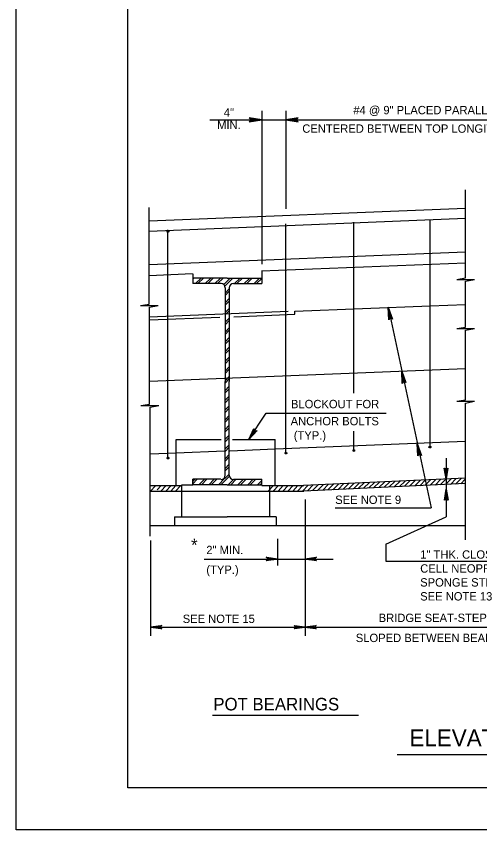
# Model space of a CAD drawing. Extents: x 640009 to 641706, y 298547 to 299735.
# Drawn here: x 640009.5 to 640175.7, y 298547.2 to 298839.2 of the extents above; entities that cross this region are included whole.
import ezdxf

# ---------------------------------------------------------------- set-up
doc = ezdxf.new("R2010")
doc.units = 0
doc.layers.add('1', color=7, linetype='Continuous')
doc.layers.add('PLT-BNDY', color=7, linetype='Continuous')

msp = doc.modelspace()

# ---------------------------------------------------------------- linework, layer by layer
at = {"layer": '1'}
for p, q in [((640049.47, 298562.17), (640049.47, 299126.17)), ((640049.47, 298562.17), (640049.47, 299126.17)), ((640097.48, 298805.29), (640097.48, 298750.25)), ((640106.11, 298805.29), (640106.11, 298770.05)), ((640078.94, 298802.06), (640270.39, 298802.06)), ((640170.61, 298745.27), (640170.61, 298776.9)), ((640057.11, 298735.87), (640057.11, 298770.62)), ((640057.11, 298765.75), (640170.61, 298770.37)), ((640057.11, 298762.12), (640170.61, 298766.74)), ((640157.86, 298684.37), (640157.86, 298766.13)), ((640106.11, 298682.25), (640106.11, 298764.69)), ((640130.48, 298703.87), (640130.48, 298765.27)), ((640063.86, 298680.5), (640063.86, 298762.5)), ((640057.11, 298750.12), (640170.61, 298754.62)), ((640097.45, 298747.8), (640170.61, 298750.74)), ((640057.11, 298746.12), (640072.65, 298746.83)), ((640072.73, 298746.8), (640072.73, 298743.25)), ((640097.48, 298747.75), (640097.48, 298743.25)), ((640085.11, 298745.25), (640072.73, 298745.25)), ((640085.11, 298745.25), (640072.73, 298745.25)), ((640072.73, 298745.25), (640072.73, 298743.25)), ((640085.11, 298745.25), (640072.73, 298745.25)), ((640072.73, 298745.25), (640072.73, 298744.25)), ((640085.11, 298745.25), (640072.73, 298745.25)), ((640072.73, 298745.25), (640072.73, 298743.25)), ((640082.86, 298743.25), (640072.73, 298743.25)), ((640082.86, 298743.25), (640072.73, 298743.25)), ((640082.86, 298743.25), (640072.73, 298743.25)), ((640085.11, 298745.25), (640097.48, 298745.25)), ((640085.11, 298745.25), (640097.48, 298745.25)), ((640085.11, 298745.25), (640097.48, 298745.25)), ((640085.11, 298745.25), (640097.48, 298745.25)), ((640087.36, 298743.25), (640097.48, 298743.25)), ((640087.36, 298743.25), (640097.48, 298743.25)), ((640087.36, 298743.25), (640097.48, 298743.25)), ((640097.48, 298745.25), (640097.48, 298743.25)), ((640097.48, 298745.25), (640097.48, 298744.25)), ((640097.48, 298745.25), (640097.48, 298743.25)), ((640167.48, 298744.77), (640170.61, 298745.27)), ((640167.48, 298744.77), (640173.86, 298744.77)), ((640170.61, 298744.12), (640173.86, 298744.77)), ((640170.61, 298735.8), (640170.61, 298744.12)), ((640170.73, 298744.77), (640170.73, 298744.77)), ((640084.36, 298741.75), (640084.36, 298708.12)), ((640084.36, 298741.75), (640084.36, 298708.12)), ((640084.36, 298741.75), (640084.36, 298708.12)), ((640085.86, 298741.75), (640085.86, 298708.12)), ((640085.86, 298741.75), (640085.86, 298708.12)), ((640085.86, 298741.75), (640085.86, 298708.12)), ((640053.98, 298735.37), (640057.11, 298735.87)), ((640053.98, 298735.37), (640060.36, 298735.37)), ((640057.23, 298734.75), (640060.36, 298735.37)), ((640057.23, 298735.37), (640057.23, 298735.37)), ((640057.23, 298700), (640057.23, 298734.75)), ((640109.36, 298733.37), (640157.86, 298735.29)), ((640142.86, 298734.75), (640158.21, 298662.75)), ((640157.86, 298735.29), (640170.61, 298735.8)), ((640170.61, 298727.63), (640170.61, 298735.8)), ((640057.23, 298731.37), (640106.98, 298733.37)), ((640057.23, 298730.25), (640082.48, 298731.25)), ((640087.48, 298731.37), (640109.36, 298732.25)), ((640109.36, 298732.25), (640109.36, 298733.37)), ((640167.48, 298727.13), (640170.61, 298727.63)), ((640167.48, 298727.13), (640173.86, 298727.13)), ((640170.61, 298726.48), (640173.86, 298727.13)), ((640170.61, 298701.5), (640170.61, 298726.48)), ((640170.73, 298727.13), (640170.73, 298727.13)), ((640057.23, 298708.25), (640170.61, 298712.76)), ((640084.36, 298674.5), (640084.36, 298708.12)), ((640084.36, 298674.5), (640084.36, 298708.12)), ((640084.36, 298674.5), (640084.36, 298708.12)), ((640085.86, 298674.5), (640085.86, 298708.12)), ((640085.86, 298674.5), (640085.86, 298708.12)), ((640085.86, 298674.5), (640085.86, 298708.12)), ((640054.11, 298699.5), (640057.23, 298700)), ((640054.11, 298699.5), (640060.61, 298699.5)), ((640057.36, 298699.5), (640057.36, 298699.5)), ((640057.48, 298698.87), (640060.61, 298699.5)), ((640057.48, 298652.62), (640057.48, 298698.87)), ((640167.48, 298701), (640170.61, 298701.5)), ((640167.48, 298701), (640173.86, 298701)), ((640170.61, 298700.35), (640173.86, 298701)), ((640170.61, 298651.25), (640170.61, 298700.35)), ((640170.73, 298701), (640170.73, 298701)), ((640092.73, 298687.12), (640099.11, 298696.75)), ((640099.11, 298696.75), (640142.11, 298696.75)), ((640130.48, 298683.25), (640130.48, 298690.25)), ((640066.86, 298670.62), (640066.86, 298687.25)), ((640066.86, 298687.25), (640082.98, 298687.25)), ((640086.98, 298687.25), (640102.36, 298687.25)), ((640102.36, 298670.75), (640102.36, 298687.25)), ((640102.36, 298683.91), (640170.61, 298686.62)), ((640057.48, 298682.12), (640066.86, 298682.44)), ((640066.86, 298682.44), (640084.11, 298683.15)), ((640086.08, 298683.23), (640102.36, 298683.91)), ((640163.61, 298680.61), (640163.61, 298659.54)), ((640082.86, 298673), (640072.73, 298673)), ((640072.73, 298671), (640072.73, 298673)), ((640082.86, 298673), (640072.73, 298673)), ((640072.73, 298671), (640072.73, 298673)), ((640082.86, 298673), (640072.73, 298673)), ((640072.73, 298671), (640072.73, 298673)), ((640087.36, 298673), (640097.48, 298673)), ((640087.36, 298673), (640097.48, 298673)), ((640087.36, 298673), (640097.48, 298673)), ((640097.48, 298671), (640097.48, 298673)), ((640097.48, 298671), (640097.48, 298673)), ((640097.48, 298671), (640097.48, 298673)), ((640170.61, 298673.35), (640112.48, 298670.75)), ((640057.48, 298670.75), (640068.73, 298670.75)), ((640068.73, 298671), (640072.73, 298671)), ((640068.73, 298670.75), (640068.73, 298659.5)), ((640085.11, 298671), (640072.73, 298671)), ((640085.11, 298671), (640072.73, 298671)), ((640085.11, 298671), (640072.73, 298671)), ((640085.11, 298671), (640097.48, 298671)), ((640085.11, 298671), (640097.48, 298671)), ((640085.11, 298671), (640097.48, 298671)), ((640097.48, 298670.75), (640100.23, 298670.75)), ((640100.23, 298670.75), (640100.23, 298659.5)), ((640100.23, 298670.75), (640112.61, 298670.75)), ((640170.61, 298671.47), (640112.61, 298668.75)), ((640057.48, 298668.75), (640112.61, 298668.75)), ((640113.11, 298665.75), (640113.11, 298616.74)), ((640123.84, 298662.75), (640158.21, 298662.75)), ((640066.23, 298659.5), (640066.23, 298656.37)), ((640066.23, 298659.5), (640085.11, 298659.5)), ((640102.73, 298659.5), (640085.11, 298659.5)), ((640102.73, 298659.5), (640102.73, 298656.37)), ((640141.96, 298649.74), (640163.61, 298659.54)), ((640057.48, 298656.37), (640170.61, 298656.37)), ((640057.61, 298651), (640057.61, 298616.74)), ((640103.11, 298651.62), (640103.11, 298642)), ((640141.96, 298649.74), (640141.96, 298643.6)), ((640076.84, 298644.37), (640103.11, 298644.37)), ((640103.11, 298644.37), (640113.11, 298644.37)), ((640113.11, 298644.37), (640123.11, 298644.37)), ((640141.96, 298643.6), (640215, 298643.6)), ((640057.61, 298619.87), (640112.98, 298619.87)), ((640112.98, 298619.87), (640234.61, 298619.87)), ((640079.8, 298588.35), (640132.14, 298588.35)), ((640146.11, 298574.16), (640205.89, 298574.16)), ((640835.47, 298562.17), (640049.47, 298562.17)), ((640835.47, 298562.17), (640049.47, 298562.17))]:
    msp.add_line(p, q, dxfattribs=at)
for points in [[(640093.24, 298801.53), (640093.41, 298801.84), (640097.48, 298802.06), (640093.24, 298801.53), (640093.03, 298801.34), (640097.48, 298802.06), (640093.41, 298802.26), (640093.26, 298802.57), (640097.48, 298802.06), (640093.03, 298802.79), (640093.26, 298802.57)], [(640110.35, 298802.6), (640110.18, 298802.29), (640106.11, 298802.06), (640110.35, 298802.6), (640110.56, 298802.79), (640106.11, 298802.06), (640110.18, 298801.86), (640110.33, 298801.56), (640106.11, 298802.06), (640110.56, 298801.34), (640110.33, 298801.56)], [(640063.85, 298762), (640063.85, 298762), (640063.85, 298762.12), (640063.98, 298762.12), (640063.98, 298762.12), (640063.98, 298762), (640063.98, 298762), (640063.98, 298761.87), (640063.85, 298761.87), (640063.85, 298761.87), (640063.73, 298762), (640063.73, 298762.12), (640063.73, 298762.12), (640063.85, 298762.12), (640063.85, 298762.25), (640063.98, 298762.25), (640064.1, 298762.12), (640064.1, 298762), (640064.1, 298761.87), (640063.98, 298761.75), (640063.98, 298761.75), (640063.85, 298761.75), (640063.73, 298761.87), (640063.6, 298762), (640063.6, 298762.12), (640063.73, 298762.12), (640063.73, 298762.25), (640063.85, 298762.25), (640063.98, 298762.25), (640064.1, 298762.25), (640064.23, 298762.12), (640064.23, 298762.12), (640064.23, 298762), (640064.23, 298761.87), (640064.1, 298761.87), (640064.1, 298761.75), (640063.98, 298761.75), (640063.85, 298761.75), (640063.85, 298761.75), (640063.73, 298761.75), (640063.6, 298761.75), (640063.6, 298761.87), (640063.6, 298762), (640063.6, 298762), (640063.6, 298762.12), (640063.6, 298762.25), (640063.73, 298762.25), (640063.85, 298762.25), (640063.98, 298762.37), (640063.98, 298762.25), (640064.1, 298762.25), (640063.85, 298762)], [(640072.73, 298744.87), (640073.11, 298745.25)], [(640073.73, 298743.25), (640075.73, 298745.25)], [(640074.61, 298743.25), (640076.61, 298745.25)], [(640077.23, 298743.25), (640079.23, 298745.25)], [(640078.11, 298743.25), (640080.11, 298745.25)], [(640080.73, 298743.25), (640082.73, 298745.25)], [(640081.61, 298743.25), (640083.61, 298745.25)], [(640083.86, 298742.87), (640086.23, 298745.25)], [(640084.23, 298742.37), (640087.11, 298745.25)], [(640087.73, 298743.25), (640089.73, 298745.25)], [(640088.61, 298743.25), (640090.61, 298745.25)], [(640091.23, 298743.25), (640093.23, 298745.25)], [(640092.11, 298743.25), (640094.11, 298745.25)], [(640094.73, 298743.25), (640096.73, 298745.25)], [(640095.61, 298743.25), (640097.48, 298745.12)], [(640097.36, 298743.25), (640097.48, 298743.37)], [(640084.36, 298739.87), (640085.86, 298741.37)], [(640084.36, 298739), (640085.86, 298740.5)], [(640084.36, 298736.37), (640085.86, 298737.87)], [(640084.36, 298735.5), (640085.86, 298737)], [(640084.36, 298732.87), (640085.86, 298734.37)], [(640143.23, 298730.43), (640143.42, 298730.62), (640142.86, 298734.75), (640143.23, 298730.43), (640143.04, 298730.25), (640142.86, 298734.75), (640143.79, 298730.81), (640144.17, 298730.62), (640142.86, 298734.75), (640144.36, 298730.43), (640144.17, 298730.62)], [(640084.36, 298732), (640085.86, 298733.5)], [(640084.36, 298729.37), (640085.86, 298730.87)], [(640084.36, 298728.5), (640085.86, 298730)], [(640084.36, 298725.87), (640085.86, 298727.37)], [(640084.36, 298725), (640085.86, 298726.5)], [(640084.36, 298722.37), (640085.86, 298723.87)], [(640084.36, 298721.5), (640085.86, 298723)], [(640084.36, 298718.87), (640085.86, 298720.37)], [(640084.36, 298718), (640085.86, 298719.5)], [(640084.36, 298715.37), (640085.86, 298716.87)], [(640084.36, 298714.5), (640085.86, 298716)], [(640084.36, 298711.87), (640085.86, 298713.37)], [(640084.36, 298711), (640085.86, 298712.5)], [(640148.09, 298707.72), (640148.28, 298707.91), (640147.72, 298711.85), (640148.09, 298707.72), (640147.91, 298707.35), (640147.72, 298711.85), (640148.66, 298707.91), (640149.03, 298707.91), (640147.72, 298711.85), (640149.22, 298707.72), (640149.03, 298707.91)], [(640084.36, 298708.37), (640085.86, 298709.87)], [(640084.36, 298707.5), (640085.86, 298709)], [(640084.36, 298704.87), (640085.86, 298706.37)], [(640084.36, 298704), (640085.86, 298705.5)], [(640084.36, 298701.37), (640085.86, 298702.87)], [(640084.36, 298700.5), (640085.86, 298702)], [(640084.36, 298697.87), (640085.86, 298699.37)], [(640084.36, 298697), (640085.86, 298698.5)], [(640084.36, 298694.37), (640085.86, 298695.87)], [(640084.36, 298693.5), (640085.86, 298695)], [(640084.36, 298690.87), (640085.86, 298692.37)], [(640084.36, 298690), (640085.86, 298691.5)], [(640095.53, 298690.31), (640095.17, 298690.31), (640092.83, 298687.25), (640095.53, 298690.31), (640095.89, 298690.49), (640092.83, 298687.25), (640094.81, 298690.67), (640094.81, 298690.85), (640092.83, 298687.25), (640094.63, 298691.21), (640094.81, 298690.85)], [(640084.36, 298687.37), (640085.86, 298688.87)], [(640084.36, 298686.5), (640085.86, 298688)], [(640084.36, 298683.87), (640085.86, 298685.37)], [(640084.36, 298683), (640085.86, 298684.5)], [(640153.64, 298681.58), (640153.83, 298681.77), (640153.27, 298685.89), (640153.64, 298681.58), (640153.45, 298681.39), (640153.27, 298685.89), (640154.2, 298681.95), (640154.58, 298681.77), (640153.27, 298685.89), (640154.77, 298681.58), (640154.58, 298681.77)], [(640157.86, 298684.5), (640157.86, 298684.62), (640157.86, 298684.62), (640157.86, 298684.62), (640157.98, 298684.62), (640157.98, 298684.5), (640157.98, 298684.5), (640157.86, 298684.37), (640157.86, 298684.37), (640157.73, 298684.37), (640157.73, 298684.5), (640157.73, 298684.62), (640157.73, 298684.62), (640157.73, 298684.75), (640157.86, 298684.75), (640157.98, 298684.75), (640157.98, 298684.62), (640158.11, 298684.5), (640158.11, 298684.37), (640157.98, 298684.37), (640157.86, 298684.25), (640157.73, 298684.25), (640157.61, 298684.37), (640157.61, 298684.5), (640157.61, 298684.62), (640157.61, 298684.75), (640157.73, 298684.75), (640157.86, 298684.75), (640157.98, 298684.75), (640158.11, 298684.75), (640158.11, 298684.75), (640158.11, 298684.62), (640158.11, 298684.5), (640158.11, 298684.37), (640158.11, 298684.37), (640157.98, 298684.25), (640157.98, 298684.25), (640157.86, 298684.25), (640157.73, 298684.25), (640157.61, 298684.25), (640157.61, 298684.37), (640157.48, 298684.37), (640157.48, 298684.5), (640157.48, 298684.62), (640157.48, 298684.62), (640157.61, 298684.75), (640157.61, 298684.75), (640157.73, 298684.87), (640157.86, 298684.87), (640157.98, 298684.87), (640157.98, 298684.75), (640157.86, 298684.5)], [(640084.36, 298680.37), (640085.86, 298681.87)], [(640106.11, 298682.37), (640106.11, 298682.5), (640106.11, 298682.5), (640106.23, 298682.5), (640106.23, 298682.5), (640106.23, 298682.37), (640106.23, 298682.37), (640106.23, 298682.25), (640106.11, 298682.25), (640105.98, 298682.25), (640105.98, 298682.37), (640105.98, 298682.5), (640105.98, 298682.5), (640106.11, 298682.5), (640106.11, 298682.62), (640106.23, 298682.62), (640106.36, 298682.5), (640106.36, 298682.37), (640106.36, 298682.25), (640106.23, 298682.12), (640106.11, 298682.12), (640105.98, 298682.12), (640105.98, 298682.25), (640105.86, 298682.37), (640105.86, 298682.5), (640105.98, 298682.62), (640105.98, 298682.62), (640106.11, 298682.62), (640106.23, 298682.62), (640106.36, 298682.62), (640106.36, 298682.5), (640106.48, 298682.5), (640106.48, 298682.37), (640106.48, 298682.25), (640106.36, 298682.25), (640106.36, 298682.12), (640106.23, 298682.12), (640106.11, 298682.12), (640105.98, 298682.12), (640105.98, 298682.12), (640105.86, 298682.25), (640105.86, 298682.25), (640105.86, 298682.37), (640105.86, 298682.5), (640105.86, 298682.5), (640105.86, 298682.62), (640105.98, 298682.62), (640106.11, 298682.75), (640106.11, 298682.75), (640106.23, 298682.62), (640106.36, 298682.62), (640106.11, 298682.37)], [(640130.48, 298683.37), (640130.48, 298683.37), (640130.48, 298683.5), (640130.48, 298683.5), (640130.61, 298683.5), (640130.61, 298683.37), (640130.61, 298683.25), (640130.61, 298683.25), (640130.48, 298683.25), (640130.36, 298683.25), (640130.36, 298683.37), (640130.36, 298683.37), (640130.36, 298683.5), (640130.48, 298683.5), (640130.48, 298683.5), (640130.61, 298683.5), (640130.73, 298683.5), (640130.73, 298683.37), (640130.73, 298683.25), (640130.61, 298683.12), (640130.48, 298683.12), (640130.36, 298683.12), (640130.23, 298683.25), (640130.23, 298683.37), (640130.23, 298683.5), (640130.23, 298683.5), (640130.36, 298683.62), (640130.48, 298683.62), (640130.61, 298683.62), (640130.73, 298683.62), (640130.73, 298683.5), (640130.73, 298683.5), (640130.73, 298683.37), (640130.73, 298683.25), (640130.73, 298683.12), (640130.73, 298683.12), (640130.61, 298683.12), (640130.48, 298683), (640130.36, 298683.12), (640130.36, 298683.12), (640130.23, 298683.12), (640130.23, 298683.25), (640130.11, 298683.37), (640130.11, 298683.37), (640130.23, 298683.5), (640130.23, 298683.62), (640130.23, 298683.62), (640130.36, 298683.62), (640130.48, 298683.62), (640130.61, 298683.62), (640130.73, 298683.62), (640130.48, 298683.37)], [(640063.86, 298680.62), (640063.86, 298680.75), (640063.86, 298680.75), (640063.98, 298680.75), (640063.98, 298680.75), (640064.11, 298680.75), (640063.98, 298680.62), (640063.98, 298680.5), (640063.86, 298680.5), (640063.86, 298680.5), (640063.73, 298680.62), (640063.73, 298680.75), (640063.86, 298680.75), (640063.86, 298680.87), (640063.98, 298680.87), (640063.98, 298680.87), (640064.11, 298680.75), (640064.11, 298680.62), (640064.11, 298680.5), (640064.11, 298680.5), (640063.98, 298680.37), (640063.86, 298680.5), (640063.73, 298680.5), (640063.61, 298680.62), (640063.61, 298680.75), (640063.73, 298680.87), (640063.86, 298680.87), (640063.86, 298681), (640063.98, 298681), (640064.11, 298680.87), (640064.23, 298680.87), (640064.23, 298680.75), (640064.23, 298680.62), (640064.23, 298680.5), (640064.23, 298680.5), (640064.11, 298680.37), (640063.98, 298680.37), (640063.98, 298680.37), (640063.86, 298680.37), (640063.73, 298680.37), (640063.61, 298680.5), (640063.61, 298680.5), (640063.61, 298680.62), (640063.61, 298680.75), (640063.61, 298680.75), (640063.61, 298680.87), (640063.73, 298680.87), (640063.86, 298681), (640063.98, 298681), (640063.98, 298681), (640064.11, 298680.87), (640063.86, 298680.62)], [(640084.36, 298679.5), (640085.86, 298681)], [(640084.36, 298676.87), (640085.86, 298678.37)], [(640084.36, 298676), (640085.86, 298677.5)], [(640164.07, 298676.88), (640163.82, 298676.75), (640163.61, 298673.12), (640164.07, 298676.88), (640164.19, 298677), (640163.61, 298673.12), (640163.45, 298676.74), (640163.19, 298676.87), (640163.61, 298673.12), (640162.94, 298676.99), (640163.19, 298676.87)], [(640072.73, 298671.37), (640074.36, 298673)], [(640072.73, 298672.25), (640073.48, 298673)], [(640074.98, 298671), (640076.98, 298673)], [(640075.86, 298671), (640077.86, 298673)], [(640078.48, 298671), (640080.48, 298673)], [(640079.36, 298671), (640081.36, 298673)], [(640081.98, 298671), (640084.11, 298673.25)], [(640082.86, 298671), (640085.98, 298674.12)], [(640084.23, 298673.25), (640085.86, 298674.87)], [(640085.48, 298671), (640087.48, 298673)], [(640086.36, 298671), (640088.36, 298673)], [(640088.98, 298671), (640090.98, 298673)], [(640089.86, 298671), (640091.86, 298673)], [(640092.48, 298671), (640094.48, 298673)], [(640093.36, 298671), (640095.36, 298673)], [(640095.98, 298671), (640097.48, 298672.5)], [(640148.73, 298670.5), (640150.73, 298672.5)], [(640150.48, 298670.5), (640152.61, 298672.62)], [(640152.36, 298670.62), (640154.48, 298672.62)], [(640154.23, 298670.62), (640156.23, 298672.75)], [(640155.98, 298670.75), (640158.11, 298672.87)], [(640157.86, 298670.87), (640159.98, 298672.87)], [(640159.73, 298670.87), (640161.73, 298673)], [(640161.48, 298671), (640163.61, 298673.12)], [(640163.36, 298671.12), (640165.48, 298673.12)], [(640165.23, 298671.12), (640167.23, 298673.25)], [(640166.98, 298671.25), (640169.11, 298673.37)], [(640168.86, 298671.37), (640170.47, 298672.98)], [(640057.73, 298668.87), (640059.23, 298670.5)], [(640059.98, 298669.25), (640061.48, 298670.75)], [(640061.36, 298668.75), (640063.23, 298670.75)], [(640063.11, 298668.75), (640064.98, 298670.75)], [(640064.86, 298668.75), (640066.73, 298670.75)], [(640066.61, 298668.75), (640068.48, 298670.75)], [(640096.86, 298671), (640097.48, 298671.62)], [(640099.86, 298668.75), (640101.73, 298670.75)], [(640101.61, 298668.75), (640103.48, 298670.75)], [(640103.36, 298668.75), (640105.23, 298670.75)], [(640105.11, 298668.75), (640106.98, 298670.75)], [(640106.86, 298668.75), (640108.73, 298670.75)], [(640108.61, 298668.75), (640110.48, 298670.75)], [(640110.36, 298668.75), (640112.23, 298670.75)], [(640112.11, 298668.75), (640114.11, 298670.87)], [(640113.86, 298668.87), (640115.98, 298671)], [(640115.73, 298669), (640117.73, 298671)], [(640117.48, 298669), (640119.61, 298671.12)], [(640119.36, 298669.12), (640121.48, 298671.25)], [(640121.23, 298669.25), (640123.23, 298671.25)], [(640122.98, 298669.25), (640125.11, 298671.37)], [(640124.86, 298669.37), (640126.98, 298671.5)], [(640126.73, 298669.5), (640128.73, 298671.5)], [(640128.48, 298669.5), (640130.61, 298671.62)], [(640130.36, 298669.62), (640132.48, 298671.62)], [(640132.23, 298669.75), (640134.23, 298671.75)], [(640133.98, 298669.75), (640136.11, 298671.87)], [(640135.86, 298669.87), (640137.98, 298671.87)], [(640137.73, 298670), (640139.73, 298672)], [(640139.48, 298670), (640141.61, 298672.12)], [(640141.36, 298670.12), (640143.48, 298672.12)], [(640143.23, 298670.25), (640145.23, 298672.25)], [(640144.98, 298670.25), (640147.11, 298672.37)], [(640146.86, 298670.37), (640148.98, 298672.37)], [(640163.19, 298665.63), (640163.43, 298665.76), (640163.61, 298669.39), (640163.19, 298665.63), (640163.07, 298665.51), (640163.61, 298669.39), (640163.81, 298665.77), (640164.06, 298665.65), (640163.61, 298669.39), (640164.31, 298665.53), (640164.06, 298665.65)], [(640099.36, 298644.87), (640099.48, 298644.62), (640103.11, 298644.37), (640099.36, 298644.87), (640099.11, 298645), (640103.11, 298644.37), (640099.48, 298644.25), (640099.36, 298644), (640103.11, 298644.37), (640099.11, 298643.75), (640099.36, 298644)], [(640116.86, 298644), (640116.73, 298644.25), (640113.11, 298644.37), (640116.86, 298644), (640117.11, 298643.75), (640113.11, 298644.37), (640116.73, 298644.62), (640116.86, 298644.87), (640113.11, 298644.37), (640117.11, 298645), (640116.86, 298644.87)], [(640061.36, 298619.37), (640061.23, 298619.62), (640057.61, 298619.87), (640061.36, 298619.37), (640061.61, 298619.25), (640057.61, 298619.87), (640061.23, 298620), (640061.36, 298620.37), (640057.61, 298619.87), (640061.61, 298620.5), (640061.36, 298620.37)], [(640109.23, 298620.37), (640109.36, 298620.12), (640112.98, 298619.87), (640109.23, 298620.37), (640109.11, 298620.5), (640112.98, 298619.87), (640109.36, 298619.75), (640109.23, 298619.37), (640112.98, 298619.87), (640109.11, 298619.25), (640109.23, 298619.37)], [(640116.73, 298619.37), (640116.61, 298619.62), (640112.98, 298619.87), (640116.73, 298619.37), (640116.98, 298619.25), (640112.98, 298619.87), (640116.61, 298620), (640116.73, 298620.37), (640112.98, 298619.87), (640116.98, 298620.5), (640116.73, 298620.37)]]:
    msp.add_lwpolyline(points, dxfattribs=at)
for centre, start, end in [((640082.91, 298741.77), 0, 90), ((640082.91, 298741.77), 0, 90), ((640082.91, 298741.77), 0, 90), ((640087.36, 298741.77), 90, 180), ((640087.36, 298741.77), 90, 180), ((640087.36, 298741.77), 90, 180), ((640082.91, 298674.45), 270, 0), ((640082.91, 298674.45), 270, 0), ((640082.91, 298674.45), 270, 0), ((640087.36, 298674.45), 180, 270), ((640087.36, 298674.45), 180, 270), ((640087.36, 298674.45), 180, 270)]:
    msp.add_arc(centre, 1.49, start, end, dxfattribs=at)
at = {"layer": 'PLT-BNDY'}
msp.add_lwpolyline([(640009.47, 299141.17), (640850.47, 299141.17), (640850.47, 298547.17), (640009.47, 298547.17)], close=True, dxfattribs=at)

# ---------------------------------------------------------------- texts
at = {"layer": '1'}
for s, height, p in [('#4 @ 9" PLACED PARALLEL TO AND', 3, (640130.35, 298804.04)), ('4"', 3, (640083.9, 298803.2)), ('MIN.', 3, (640081.5, 298798.71)), ('CENTERED BETWEEN TOP LONGITUDINAL SLAB BARS', 3, (640112.04, 298797.41)), ('BLOCKOUT FOR', 3, (640107.98, 298698.5)), ('ANCHOR BOLTS', 3, (640107.86, 298692.37)), ('(TYP.)', 3, (640108.98, 298687.25)), ('SEE NOTE 9', 3, (640123.85, 298664.14)), ('*', 4.46, (640072.16, 298647.19)), ('2" MIN.', 3, (640077.62, 298646.11)), ('1" THK. CLOSED', 3, (640154.33, 298644.48)), (' (TYP.)', 3, (640076.51, 298639.03)), ('CELL NEOPRENE', 3, (640154.33, 298639.48)), ('SPONGE STRIP (CONT.),', 3, (640154.33, 298634.48)), ('SEE NOTE 13', 3, (640154.33, 298629.48)), ('SEE NOTE 15', 3, (640069.15, 298621.4)), ('BRIDGE SEAT-STEPPED OR', 3, (640139.43, 298621.75)), ('SLOPED BETWEEN BEARING AREAS', 3, (640131.23, 298614.55)), ('POT BEARINGS', 4.5, (640080.14, 298590.01)), ('ELEVATION', 6, (640150.49, 298577.16))]:
    msp.add_text(s, height=height, dxfattribs=at).set_placement(p)

doc.saveas('drawing.dxf')
